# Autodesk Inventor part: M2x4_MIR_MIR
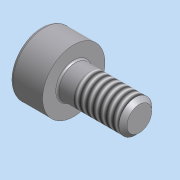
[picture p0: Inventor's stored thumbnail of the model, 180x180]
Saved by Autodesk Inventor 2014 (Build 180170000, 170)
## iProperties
Created: 2015-05
Part Number: M2x4_MIR_MIR
Material: 일반
Vendor: CBT Solutions
Document SubType Name: 모델링
Designer: Administrator
Appearance: 기본값
Company: 한국ATC센터
Author: KYOUNG IL JANG
Comments: 파생
d0: 1.000 ul
d0_1: 1.000 ul
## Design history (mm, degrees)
derived "M2x4_MIR.ipt"
feature "솔리드1::M2x4_MIR.ipt"
tag "피쳐 태그1"
node "솔리드1"
other parameters: "d0" = 1, "d0_1" = 1
